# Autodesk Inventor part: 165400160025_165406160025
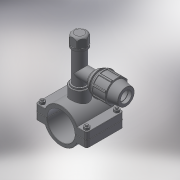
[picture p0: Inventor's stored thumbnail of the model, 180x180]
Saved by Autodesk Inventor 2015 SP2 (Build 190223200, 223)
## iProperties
Created: 2017-05
Part Number: 165400160025_165406160025
Material: Generic
Description: PLASSON TAPPER FOR PE+PVC PIPE 160-25
Document SubType Name: Modeling
Designer: KIM
Density: 1 g/cm^3
Appearance: Default
Author: KIM
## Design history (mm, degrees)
derived "16540.ipt"
feature "Solid1::16540.ipt"
feature "Solid2::16540.ipt"
tag "TaggingFeature1"
body "Solid1"
other parameters: "d0" = 176, "d1" = 223, "d4" = 145, "d5" = 0, "d6" = 11.15, "d7" = 223, "d8" = 0.1, "d10" = 0, "d11" = 1.6, "d14" = 39.3783, "d20" = 1.6, "d23" = 1.6, "d36" = 15, "d37" = 12, "d38" = 88, "d39" = 0, "d40" = 3, "d41" = 5, "d42" = 0, "d44" = 3, "d45" = 0, "d46" = 1.6, "d51" = 112, "d52" = 30.291, "d53" = 21, "d54" = 0, "d55" = 25, "d57" = 0, "d58" = 172.8, "d60" = 0, "d62" = 15, "d63" = 12, "d66" = 121, "d67" = 25, "d68" = 8.75, "d69" = 21, "d70" = 54, "d71" = 40.5, "d72" = 1.5, "d73" = 43.2, "d74" = 120 deg, "d75" = 37.5, "d76" = 10 deg, "d77" = 48.6, "d78" = 31.5, "d79" = 61, "d81" = 105, "d82" = 6.1, "d87" = 15, "d90" = 50.22, "d91" = 35 deg, "d92" = 17.5 deg, "d94" = 0, "d96" = 360 deg, "d98" = 0.5, "d99" = 67.1, "d100" = 27.2619, "d101" = 135 deg, "d102" = 1.08, "d105" = 2.7, "d106" = 0, "d107" = 0.1, "d108" = 27.2619, "d109" = 33.3201, "d111" = 26.4, "d112" = 6.6, "d113" = 3.5, "d116" = 0, "d118" = 21, "d119" = 0, "d121" = 132, "d122" = 59, "B_" = 25, "G_" = 30.291, "A_" = 112, "L_" = 223, "L_1" = 145, "l_2" = 21, "d_1" = 25, "E_" = 54, "l_" = 61, "H_" = 105, "H_1" = 59, "H_2" = 132
